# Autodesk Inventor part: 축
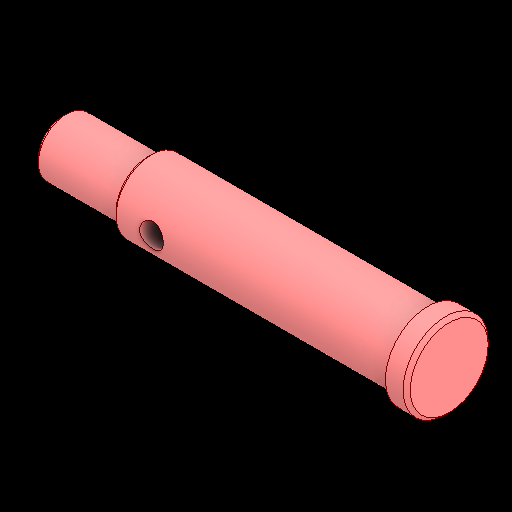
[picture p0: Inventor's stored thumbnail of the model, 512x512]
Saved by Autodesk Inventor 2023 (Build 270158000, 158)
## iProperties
Created: 2025-01
Part Number: 축
Material: 강철, 탄소
Document SubType Name: Modeling
Designer: 강의실01
Density: 7.85 g/cm^3
Appearance: 기본값
Author: jhkim
Sending System: Autodesk Inventor 2025
Preprocessor: ST-DEVELOPER v20
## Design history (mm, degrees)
feature "솔리드1"
node "솔리드2"
